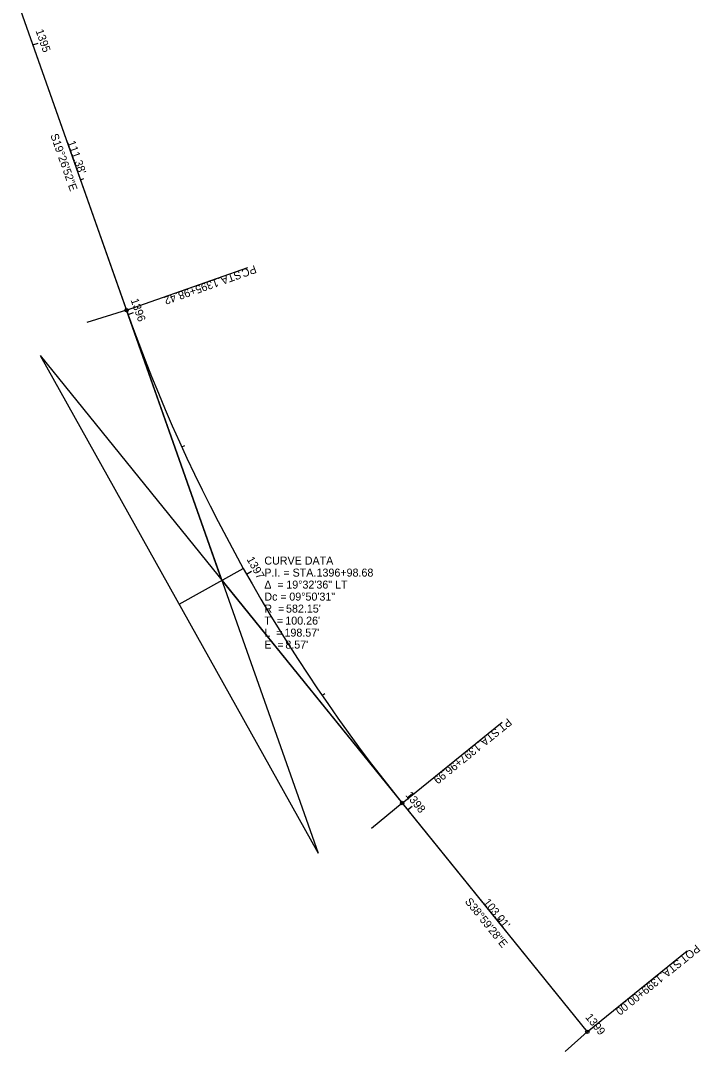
# Model space of a CAD drawing. Extents: x 208719 to 209081, y 284970 to 285717.
# Drawn here: x 208843.5 to 209081.4, y 284970.2 to 285330.9 of the extents above; entities that cross this region are included whole.
import ezdxf

# ---------------------------------------------------------------- set-up
doc = ezdxf.new("R2010")
doc.units = 0
for name, color, linetype in [('GE_P_Alignment', 7, 'Continuous'), ('GE_P_Alignment_100_Bearings', 7, 'Continuous'), ('GE_P_Alignment_100_Cardinal_Points', 7, 'Continuous'), ('GE_P_Alignment_100_Curve_Data', 7, 'Continuous'), ('GE_P_Alignment_100_Distances', 7, 'Continuous'), ('SC_Scratch1', 7, 'Continuous'), ('SC_Scratch2', 7, 'Continuous')]:
    doc.layers.add(name, color=color, linetype=linetype)

msp = doc.modelspace()

# ---------------------------------------------------------------- linework, layer by layer
at = {"layer": 'GE_P_Alignment'}
for p, q in [((208843.51, 285334.58), (208880.59, 285229.56)), ((208977.06, 285057.09), (209041.87, 284977.03))]:
    msp.add_line(p, q, dxfattribs=at)
msp.add_arc((209429.53, 285423.38), 582.15, 199.4477, 218.99109, dxfattribs=at)
msp.add_arc((209429.53, 285423.38), 582.15, 199.4477, 218.99109, dxfattribs=at)
at = {"layer": 'GE_P_Alignment_100_Bearings'}
for p, q in [((208880.59, 285229.56), (208923.03, 285244.54)), ((208977.06, 285057.09), (209012.03, 285085.41)), ((209041.87, 284977.03), (209076.85, 285005.34))]:
    msp.add_line(p, q, dxfattribs=at)
for centre in [(208880.59, 285229.56), (208977.06, 285057.09), (209041.87, 284977.03)]:
    msp.add_circle(centre, 0.6, dxfattribs=at)
at = {"layer": 'GE_P_Alignment_100_Distances'}
for p, q in [((208847.83, 285322.36), (208849.71, 285323.03)), ((208864.47, 285275.21), (208865.6, 285275.61)), ((208881.12, 285228.07), (208883.01, 285228.74)), ((208899.9, 285181.74), (208900.99, 285182.24)), ((208922.58, 285137.2), (208924.32, 285138.18)), ((208949, 285094.77), (208949.99, 285095.45)), ((208978.95, 285054.75), (208980.51, 285056.01)), ((209010.41, 285015.89), (209011.34, 285016.65)), ((209041.87, 284977.03), (209043.43, 284978.29))]:
    msp.add_line(p, q, dxfattribs=at)
at = {"layer": 'SC_Scratch1'}
for p, q in [((208843.51, 285334.58), (208947.67, 285039.59)), ((208880.59, 285229.56), (208866.74, 285225.26)), ((208913.97, 285135.02), (208880.59, 285229.56)), ((208850.3, 285213.68), (209041.87, 284977.03)), ((208850.3, 285213.68), (208947.67, 285039.59)), ((208898.98, 285126.64), (208921.45, 285139.2)), ((208913.97, 285135.02), (208977.06, 285057.09)), ((208977.06, 285057.09), (208966.37, 285048.15)), ((208977.06, 285057.09), (209041.87, 284977.03)), ((209041.87, 284977.03), (209034.14, 284970.18))]:
    msp.add_line(p, q, dxfattribs=at)

# ---------------------------------------------------------------- texts
at = {"layer": 'GE_P_Alignment_100_Bearings'}
for s, rotation, p in [(' STA. ', 199.4477, (208921.11, 285243.82)), ('PC', 199.4477, (208925.44, 285245.35)), ('1395+98.42', 199.4477, (208912.2, 285240.67)), ('PT', 218.9911, (209014, 285086.95)), (' STA. ', 218.9911, (209010.57, 285084.17)), ('1397+96.99', 218.9911, (209003.22, 285078.22)), ('POT', 218.9911, (209079.92, 285007.77)), (' STA. ', 218.9911, (209074.32, 285003.24)), ('1399+00.00', 218.9911, (209066.98, 284997.3))]:
    msp.add_text(s, height=2.8, rotation=rotation, dxfattribs=at).set_placement(p)
at = {"layer": 'GE_P_Alignment_100_Cardinal_Points'}
for s, p in [('CURVE DATA', (208928.82, 285140.53)), ('P.I. = STA. ', (208928.82, 285136.33)), ('1396+98.68', (208947.09, 285136.33)), ('Δ  = ', (208928.82, 285132.13)), ('19°32\'36" LT', (208936.5, 285132.13)), ('Dc = ', (208928.82, 285127.93)), ('09°50\'31"', (208937.56, 285127.93)), ('R  = ', (208928.82, 285123.73)), ("582.15'", (208936.41, 285123.73)), ('T  = ', (208928.82, 285119.53)), ("100.26'", (208936.16, 285119.53)), ('L  = ', (208928.82, 285115.33)), ("198.57'", (208935.87, 285115.33)), ('E  = ', (208928.82, 285111.13)), ("8.57'", (208936.17, 285111.13))]:
    msp.add_text(s, height=2.8, dxfattribs=at).set_placement(p)
at = {"layer": 'GE_P_Alignment_100_Curve_Data'}
for s, rotation, p in [("111.38'", 289.4477, (208859.87, 285288.38)), ("103.01'", 308.9911, (209005.29, 285022.28))]:
    msp.add_text(s, height=2.8, rotation=rotation, dxfattribs=at).set_placement(p)
at = {"layer": 'GE_P_Alignment_100_Distances'}
for s, rotation, p in [('1395', 289.4477, (208848.71, 285327.36)), ('1396', 289.6035, (208881.98, 285233.12)), ('1397', 299.4455, (208922.53, 285142.38)), ('1398', 308.9911, (208978.09, 285059.79)), ('1399', 308.9911, (209041.02, 284982.05))]:
    msp.add_text(s, height=2.8, rotation=rotation, dxfattribs=at).set_placement(p)
at = {"layer": 'SC_Scratch2'}
for s, rotation, p in [('S19°26\'52"E', 289.4477, (208853.88, 285290.79)), ('S38°59\'28"E', 308.9911, (208998.85, 285022.54))]:
    msp.add_text(s, height=2.8, rotation=rotation, dxfattribs=at).set_placement(p)

doc.saveas('drawing.dxf')
